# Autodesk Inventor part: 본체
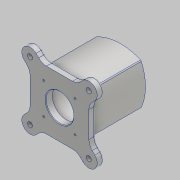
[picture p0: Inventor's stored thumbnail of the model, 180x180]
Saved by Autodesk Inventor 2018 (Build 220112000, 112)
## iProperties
Created: 2022-01
Part Number: 본체
Material: 알루미늄 6061
Document SubType Name: Modeling
Designer: home
Density: 2.7 g/cm^3
Appearance: 알루미늄 - 평지
Mass: 1224.09 g
Surface Area: 906.669 cm^2
Volume: 453.368 cm^3
Author: home
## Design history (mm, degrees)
sketch "스케치1"
  geometry: L1 (31.787, 53)-(-31.787, 53); L2 (-53, 31.787)-(-53, -31.787); L3 (-31.787, -53)-(31.787, -53); L4 (53, -31.787)-(53, 31.787); L5 (0, 0)-(71, 0); L6 (63.607, 42.393)-(53, 31.787); L7 (42.393, 63.607)-(31.787, 53); L8 (-42.393, 63.607)-(-31.787, 53); L9 (-63.607, 42.393)-(-53, 31.787); L10 (-63.607, -42.393)-(-53, -31.787); L11 (-42.393, -63.607)-(-31.787, -53); L12 (42.393, -63.607)-(31.787, -53); L13 (63.607, -42.393)-(53, -31.787); A1 r 15 centre (53, 53) between (63.607, 42.393) and (42.393, 63.607); A2 r 15 centre (-53, 53) between (-42.393, 63.607) and (-63.607, 42.393); A3 r 15 centre (-53, -53) between (-63.607, -42.393) and (-42.393, -63.607); A4 r 15 centre (53, -53) between (42.393, -63.607) and (63.607, -42.393); 6 further points
  constraints: 26 end point, 8 point on circle, 8 tangent, 4 centre point, 4 parallel, 3 coincident, 2 horizontal, 2 perpendicular, 1 equal radius
  dimensions: "d9" = 30 distance between parallel lines of L12 L13; "d10" = 30 distance between parallel lines of L10 L11; "d11" = 30 distance between parallel lines of L8 L9; "d17" = 106 distance of point (-53, -53) point (-53, 53) (derived); "d18" = 15 radius of A1; "d19" = 135 deg angle of L4 L13; "d20" = 90 deg angle of L7 L13; "d21" = 106 distance between parallel lines of L4 L2; "d22" = 53 distance between parallel lines of L5 L1; "d23" = 53 distance between parallel lines of L5 L3; "d24" = 15 distance from line of L5.start L13; "d25" = 53 distance from line of L5.start L4; "d26" = 15 distance from line of L5.start L6; "d27" = 15 distance from line of L5.start L7; "d28" = 15 distance from line of point (79, -79) L13; "d29" = 26 distance from line of point (79, -79) L4; "d30" = 35.20458 distance from line of L5.end L13; "d31" = 59.95332 distance from line of L6.start L13; "d32" = 10.6066 distance from line of L13.start L4; "d33" = 95.3934 distance from line of L8.start L4; "d34" = 89.95332 distance from line of L11.start L13; "d35" = 15 distance from line of point (-79, 79) L13; "d36" = 132 distance from line of point (-79, 79) L4; "d37" = 126.72287 distance from line of point (-79, -79) L13; "d38" = 132 distance from line of point (-79, -79) L4
extrude "돌출1" new body sketch "스케치1" distance "d39" = 12; taper "d40" = 0 deg
sketch "스케치3"
  geometry: L1 (-45, -45)-(45, -45); L2 (45, -45)-(45, 45); L3 (45, 45)-(-45, 45); L4 (-45, 45)-(-45, -45); L5 (-45, -45)-(45, 45); L6 (45, -45)-(-45, 45); A1 r 90 centre (0, 45) between (-45, -32.942) and (37.029, -37.029); A2 r 90 centre (0, -45) between (37.029, 37.029) and (-45, 32.942); A3 r 90 centre (-45, 0) between (37.029, -37.029) and (32.942, 45); 1 further point
  constraints: 12 end point, 8 point on circle, 4 midpoint, 3 centre point, 3 point on line, 2 parallel, 1 horizontal, 1 perpendicular, 1 tangent
  dimensions: "d47" = 90 distance of L3.end L2.end; "d48" = 90 distance of L2.end L1.end; "d49" = 180 diameter of A1; "d51" = 180 diameter of A3; "d52" = 180 diameter of A2
extrude "돌출3" join sketch "스케치3" distance "d53" = 98; taper "d54" = 0 deg
sketch "스케치4"
  geometry: L1 (37.029, 110)-(-45, 110) reference; L2 (-31.787, 0)-(31.787, 0) reference; L3 (0, 110)-(0, 0); L4 (-25, 110)-(-25, 98); L5 (-25, 98)-(-34, 98); L6 (-37, 95)-(-37, 15); L7 (-34, 12)-(-25, 12); L8 (-25, 12)-(-25, 0); A1 r 3 centre (-34, 95) between (-34, 98) and (-37, 95); A2 r 3 centre (-34, 15) between (-37, 15) and (-34, 12); 2 further points
  constraints: 12 end point, 7 point on line, 4 perpendicular, 4 point on circle, 4 tangent, 2 centre point, 2 vertical, 1 equal radius
  dimensions: "d55" = 50 diameter of L4 L3; "d56" = 74 diameter of L6 L3; "d57" = 50 diameter of L8 L3; "d58" = 86 distance of point (-37, 98) point (-37, 12); "d59" = 12 distance of L4.start L4.end; "d61" = 3 radius of A1
revolve "회전1" sketch "스케치4" stored, may be unused: angle "d60" = 90 deg
chamfer "모따기1" distance "d62" = 1; stored, may be unused: second distance "d63" = 2, angle "d64" = 45 deg
node "작업 평면1"
sketch "스케치5"
  geometry: L1 (0, -31.787)-(0, 31.787) reference; C1 r 20 at (61, 0); 2 further points
  constraints: 1 centre point, 1 horizontal alignment, 1 midpoint
  dimensions: "d67" = 40 diameter of C1; "d68" = 61 distance of point (0, 0) C1.centre
extrude "돌출4" join sketch "스케치5" stored distance "d69" = 98; taper "d70" = 10 deg
sketch "스케치6"
  geometry: C1 r 20 at (0, 0) reference; C2 r 12 at (0, 0); 1 further point
  constraints: 1 centre point, 1 coincident
  dimensions: "d71" = 24 diameter of C2
extrude "돌출5" cut sketch "스케치6" distance "d72" = 13; taper "d73" = 0 deg
sketch "스케치7"
  geometry: C1 r 12 at (0, 0) reference; C2 r 20 at (0, 0) reference; C3 r 15 at (0, 0); 1 further point
  constraints: 1 centre point, 1 coincident
  dimensions: "d74" = 30 diameter of C3
extrude "돌출6" cut sketch "스케치7" distance "d75" = 15; taper "d76" = 0 deg
fillet "모깎기1" dims "d77" = 3
sketch "스케치8"
  geometry: L1 (-53, -31.787)-(-63.607, -42.393) reference; A1 r 15 centre (-53, -53) between (-63.607, -42.393) and (-42.393, -63.607) reference; A2 r 15 centre (-53, 53) between (-42.393, 63.607) and (-63.607, 42.393) reference; A3 r 15 centre (53, 53) between (63.607, 42.393) and (42.393, 63.607) reference; A4 r 15 centre (53, -53) between (42.393, -63.607) and (63.607, -42.393) reference; 5 further points
  constraints: 4 coincident
hole "구멍1" sketch "스케치8" at (-53, -53), (-53, 53), (53, 53), (53, -53) diameter "d78" = 9; stored, may be unused: countersink angle "d82" = 90 deg, drill point angle "d84" = 0 deg; dims "d79" = 6, "d80" = 18, "d81" = 2, "d83" = 12
fillet "모깎기2" dims "d85" = 3
fillet "모깎기4" dims "d87" = 3
sketch "스케치9" dims "d89" = 80
  geometry: L1 (0, 0)-(-28.284, -28.284); L2 (0, 0)-(-45, 0); 2 further points
  constraints: 4 end point, 2 coincident, 1 horizontal, 3 other
  dimensions: "d90" = 45 deg angle of L1 L2
hole "구멍2" sketch "스케치9" at (-28.284, -28.284) diameter "d92" = 3.242; stored, may be unused: countersink angle "d96" = 90 deg, drill point angle "d98" = 118 deg; dims "d93" = 9, "d94" = 18, "d95" = 2, "d97" = 11
sketch "스케치10"
  geometry: L1 (0, 0)-(-40, 0); L2 (0, 0)-(-28.284, -28.284); A1 r 40 centre (0, 0) between (-40, 0) and (-28.284, -28.284); 2 further points
  constraints: 4 end point, 2 coincident, 2 point on circle, 1 centre point, 1 horizontal
  dimensions: "d102" = 80 diameter of A1; "d103" = 45 deg angle of L1 L2
hole "구멍3" sketch "스케치10" at (-28.284, -28.284) diameter "d104" = 3.242; stored, may be unused: countersink angle "d108" = 90 deg, drill point angle "d110" = 118 deg; dims "d105" = 9, "d106" = 18, "d107" = 2, "d109" = 11
fillet "모깎기5" dims "d114" = 20
fillet "모깎기6" dims "d115" = 3
node "작업 평면3"
sketch "스케치13"
  geometry: L1 (110, 63.396)-(110, 37.308) reference; 4 further points; 1 other entity
  constraints: 2 other
  dimensions: "d119" = 61 distance from line of L1 point (49, -2.147); "d120" = 55 distance of point (49, -2.147) point (49, 52.853)
feature "엠보싱2" sketch "스케치13" dims "d2" = 30, "d9" = 30, "d10" = 30, "d11" = 30, "d17" = 106 (derived), "d18" = 15, "d19" = 135 deg, "d20" = 90 deg, "d21" = 106, "d22" = 53, "d23" = 53, "d24" = 15, "d25" = 53, "d26" = 15, "d27" = 15, "d28" = 15, "d29" = 26, "d30" = 35.20458, "d31" = 59.95332, "d32" = 10.6066, "d33" = 95.3934, "d34" = 89.95332, "d35" = 15, "d36" = 132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
node "솔리드1"
pattern_circular "원형 패턴1" dims angle "d100" = 360 deg
pattern_circular "원형 패턴2" dims angle "d112" = 360 deg
node "투영된 루프1"
node "투영된 루프2"
other parameters: "d5" = 15, "d65" = -55
